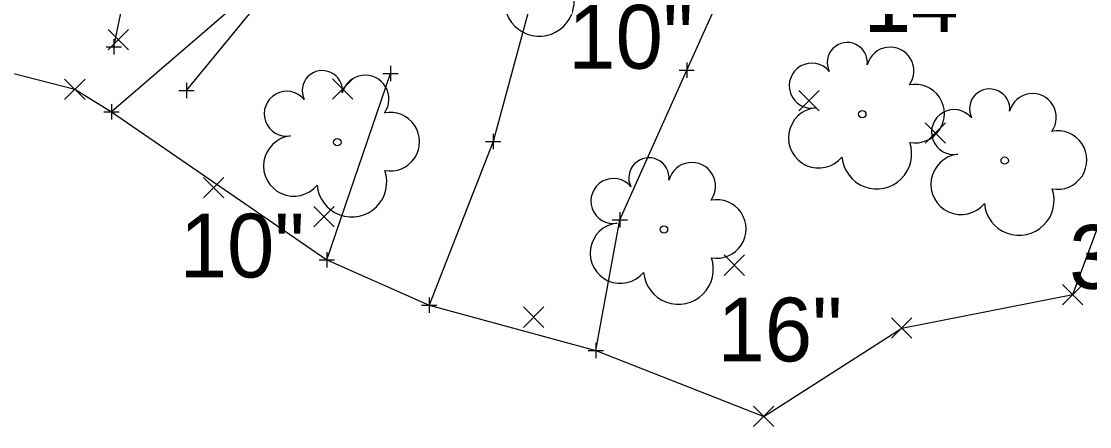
# Model space of a CAD drawing. Extents: x 2005176 to 2005823, y 572472 to 572942.
# Drawn here: x 2005494.7 to 2005564.6, y 572471.7 to 572498.2 of the extents above; entities that cross this region are included whole.
import ezdxf

# ---------------------------------------------------------------- set-up
doc = ezdxf.new("R2010")
doc.units = 0
for name, color, linetype in [('GE_X_Alignment_100_Stations', 7, 'Continuous'), ('GE_X_Alignment_500_Bearings', 7, 'Continuous'), ('GE_X_Alignment_500_Cardinal_Points', 7, 'Continuous'), ('SV_P_Mon_Cells_Set', 7, 'Continuous'), ('SV_X_Random_Point', 7, 'Continuous'), ('SV_X_Shot_Marker', 7, 'Continuous'), ('SV_X_Terrain_Boundary', 7, 'Continuous'), ('VG_X_Text', 7, 'Continuous')]:
    doc.layers.add(name, color=color, linetype=linetype)

msp = doc.modelspace()

# ---------------------------------------------------------------- linework, layer by layer
at = {"layer": 'GE_X_Alignment_100_Stations'}
msp.add_lwpolyline([(2005526.126, 572569.752), (2005528.014, 572562.539), (2005526.605, 572553.625), (2005531.765, 572536.046), (2005521.073, 572519.95), (2005516.881, 572512.197), (2005511.963, 572508.178), (2005509.477, 572499.914), (2005500.59, 572492.24)], dxfattribs=at)
at = {"layer": 'GE_X_Alignment_500_Bearings'}
for points in [[(2005500.74, 572496.501), (2005502.666, 572505.833), (2005503.248, 572514.147), (2005499.084, 572526.483), (2005502.215, 572545.864), (2005503.875, 572554.617), (2005506.82, 572561.115), (2005509.657, 572562.142), (2005510.083, 572567.796)], [(2005532.268, 572476.648), (2005533.838, 572485.174), (2005538.205, 572494.974), (2005543.28, 572506.202), (2005549.269, 572518.298), (2005553.939, 572530.22), (2005565.743, 572541.873), (2005569.086, 572544.678)], [(2005514.667, 572482.565), (2005518.832, 572494.749)]]:
    msp.add_lwpolyline(points, dxfattribs=at)
at = {"layer": 'GE_X_Alignment_500_Cardinal_Points'}
for points in [[(2005505.489, 572493.647), (2005512.611, 572502.332), (2005515.602, 572509.525), (2005522.377, 572518.182), (2005528.142, 572526.059), (2005534.669, 572529.98), (2005534.351, 572537.981), (2005532.172, 572545.253), (2005530.581, 572546.261), (2005528.258, 572551.573), (2005532.711, 572557)], [(2005563.298, 572546.993), (2005548.706, 572539.064), (2005542.148, 572542.622), (2005536.485, 572536.442), (2005540.134, 572531.756), (2005536.945, 572523.241), (2005533.482, 572507.768), (2005528.663, 572501.824), (2005525.549, 572490.297), (2005521.368, 572479.609)]]:
    msp.add_lwpolyline(points, dxfattribs=at)
at = {"layer": 'SV_P_Mon_Cells_Set'}
for p, q in [((2005500.74, 572497.001), (2005500.74, 572496.001)), ((2005500.24, 572496.501), (2005501.24, 572496.501)), ((2005500.74, 572496.501), (2005500.74, 572496.501)), ((2005538.205, 572495.474), (2005538.205, 572494.474)), ((2005518.332, 572494.749), (2005519.332, 572494.749)), ((2005518.832, 572495.249), (2005518.832, 572494.249)), ((2005518.832, 572494.749), (2005518.832, 572494.749)), ((2005537.705, 572494.974), (2005538.705, 572494.974)), ((2005538.205, 572494.974), (2005538.205, 572494.974)), ((2005505.489, 572494.147), (2005505.489, 572493.147)), ((2005504.989, 572493.647), (2005505.989, 572493.647)), ((2005505.489, 572493.647), (2005505.489, 572493.647)), ((2005500.59, 572492.74), (2005500.59, 572491.74)), ((2005500.09, 572492.24), (2005501.09, 572492.24)), ((2005500.59, 572492.24), (2005500.59, 572492.24)), ((2005525.549, 572490.797), (2005525.549, 572489.797)), ((2005525.049, 572490.297), (2005526.049, 572490.297)), ((2005525.549, 572490.297), (2005525.549, 572490.297)), ((2005533.838, 572485.674), (2005533.838, 572484.674)), ((2005533.338, 572485.174), (2005534.338, 572485.174)), ((2005533.838, 572485.174), (2005533.838, 572485.174)), ((2005514.667, 572483.065), (2005514.667, 572482.065)), ((2005514.167, 572482.565), (2005515.167, 572482.565)), ((2005514.667, 572482.565), (2005514.667, 572482.565)), ((2005521.368, 572480.109), (2005521.368, 572479.109)), ((2005520.868, 572479.609), (2005521.868, 572479.609)), ((2005521.368, 572479.609), (2005521.368, 572479.609)), ((2005531.768, 572476.648), (2005532.768, 572476.648)), ((2005532.268, 572477.148), (2005532.268, 572476.148)), ((2005532.268, 572476.648), (2005532.268, 572476.648))]:
    msp.add_line(p, q, dxfattribs=at)
at = {"layer": 'SV_X_Random_Point'}
for p, q in [((2005500.363, 572496.292), (2005501.696, 572497.627)), ((2005500.363, 572497.627), (2005501.696, 572496.292)), ((2005497.515, 572493.047), (2005498.849, 572494.382)), ((2005497.515, 572494.382), (2005498.849, 572493.047)), ((2005515.031, 572493.065), (2005516.365, 572494.4)), ((2005515.031, 572494.4), (2005516.365, 572493.065)), ((2005545.549, 572492.308), (2005546.882, 572493.643)), ((2005545.549, 572493.643), (2005546.882, 572492.308)), ((2005553.807, 572490.197), (2005555.14, 572491.532)), ((2005553.807, 572491.532), (2005555.14, 572490.197)), ((2005506.606, 572486.615), (2005507.939, 572487.95)), ((2005506.606, 572487.95), (2005507.939, 572486.615)), ((2005513.819, 572484.726), (2005515.153, 572486.061)), ((2005513.819, 572486.061), (2005515.153, 572484.726)), ((2005540.664, 572481.552), (2005541.997, 572482.887)), ((2005540.664, 572482.887), (2005541.997, 572481.552)), ((2005562.793, 572479.63), (2005564.126, 572480.965)), ((2005562.793, 572480.965), (2005564.126, 572479.63)), ((2005527.526, 572478.155), (2005528.859, 572479.49)), ((2005527.526, 572479.49), (2005528.859, 572478.155)), ((2005551.605, 572477.442), (2005552.938, 572478.777)), ((2005551.605, 572478.777), (2005552.938, 572477.442)), ((2005542.577, 572471.668), (2005543.911, 572473.003)), ((2005542.577, 572473.003), (2005543.911, 572471.668))]:
    msp.add_line(p, q, dxfattribs=at)
at = {"layer": 'SV_X_Shot_Marker'}
for centre in [(2005549.693, 572492.09), (2005515.354, 572490.254), (2005559.006, 572489.055), (2005536.72, 572484.553)]:
    msp.add_circle(centre, 0.24, dxfattribs=at)
for centre, radius, start, end in [((2005528.564, 572499.473), 2.284, 184.94757, 19.45715), ((2005548.71, 572495.458), 1.317, 354.0047, 205.97412), ((2005551.519, 572494.92), 1.553, 323.82996, 165.0376), ((2005546.384, 572493.955), 1.471, 39.06254, 279.54124), ((2005514.371, 572493.622), 1.317, 354.0047, 205.97412), ((2005517.181, 572493.083), 1.553, 323.82996, 165.0376), ((2005553.154, 572492.126), 1.915, 259.14531, 101.45961), ((2005512.045, 572492.118), 1.471, 39.06254, 279.54124), ((2005558.022, 572492.423), 1.317, 354.0047, 205.97412), ((2005560.832, 572491.884), 1.553, 323.82996, 165.0376), ((2005518.815, 572490.29), 1.915, 259.14531, 101.45961), ((2005546.84, 572490.542), 1.974, 96.17219, 320.57371), ((2005555.696, 572490.919), 1.471, 39.06254, 279.54124), ((2005512.501, 572488.705), 1.974, 96.17219, 320.57371), ((2005562.466, 572489.091), 1.915, 259.14531, 101.45961), ((2005550.64, 572489.485), 2.284, 184.94757, 19.45715), ((2005535.736, 572487.921), 1.317, 354.0047, 205.97412), ((2005556.152, 572487.506), 1.974, 96.17219, 320.57371), ((2005516.301, 572487.649), 2.284, 184.94757, 19.45715), ((2005538.546, 572487.382), 1.553, 323.82996, 165.0376), ((2005533.411, 572486.417), 1.471, 39.06254, 279.54124), ((2005559.952, 572486.45), 2.284, 184.94757, 19.45715), ((2005540.18, 572484.589), 1.915, 259.14531, 101.45961), ((2005533.867, 572483.005), 1.974, 96.17219, 320.57371), ((2005537.666, 572481.948), 2.284, 184.94757, 19.45715)]:
    msp.add_arc(centre, radius, start, end, dxfattribs=at)
at = {"layer": 'SV_X_Terrain_Boundary'}
msp.add_lwpolyline([(2005414.704, 572571.993), (2005458.479, 572515.558), (2005472.631, 572507.15), (2005476.652, 572499.232), (2005498.182, 572493.714), (2005500.59, 572492.24), (2005514.667, 572482.565), (2005521.368, 572479.609), (2005532.268, 572476.648), (2005543.244, 572472.335), (2005552.271, 572478.109), (2005563.459, 572480.297), (2005570.757, 572499.94), (2005575.287, 572509.4), (2005587.95, 572518.639), (2005591.142, 572529.855), (2005622.825, 572562.218), (2005632.872, 572562.762), (2005676.665, 572561.819)], dxfattribs=at)

# ---------------------------------------------------------------- texts
at = {"layer": 'VG_X_Text'}
for s, p in [('14"', (2005549.78, 572497.471)), ('10"', (2005530.453, 572495.063)), ('10"', (2005505.04, 572481.415)), ('30"', (2005563.222, 572480.68)), ('16"', (2005540.217, 572475.93))]:
    msp.add_text(s, height=4.1667, dxfattribs=at).set_placement(p)

doc.saveas('drawing.dxf')
